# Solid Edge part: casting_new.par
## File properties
Author: Sarvanan
Template: Sync Iso Part.par
Last saved by: Sham
Revision: 25
Application: Solid Edge
Accuracy: 0.990
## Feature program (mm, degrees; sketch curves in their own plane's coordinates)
sketch for "Hole_1" plane through (160.4937, 0.1465, 63.8379) normal (0, 0, 1) x-axis (1, 0, 0)
  hole centre (-0.3699, -0.1465) bore radius 6
hole "Hole_1" diameter 12 through
sketch for "unnamed Hole 1" plane through (81.754, 0.1465, 63.8379) normal (0, 0, 1) x-axis (-1, 0, 0)
  hole centre (-0.3699, -0.1465) bore radius 6
hole "unnamed Hole 1" through
pattern "unnamed Pattern 1" of "Hole_1", "unnamed Hole 1"
Other named dimensions: "Hole_3": FiniteDepth = 8 mm; VBottomAngle = 118 deg; Diameter = 8 mm
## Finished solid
Body 1: solid body, 44 faces, 112 edges, 68 vertices.
  Faces by surface: plane 28, cylinder 10, cone 4, torus 2
  Edges by curve: line 82, circle 25, intersection 5
Bounding box of the edges (mm; curved faces can reach further): 208.000 x 56.000 x 68.000, from (17.1238, -28, -4.1621) to (225.1238, 28, 63.8379).
Cylindrical faces by radius (mm): R4 x1, R5 x4, R6 x2, R24 x1, R54 x2
Conical faces (half-angle, radius in mm at the cone's reference point): 45 deg R6 x4
Toroidal faces (ring radius, tube radius in mm): R62 r8 x2
Planar faces by outward normal: +x 3, +y 3, +z 7, -x 3, -y 3, -z 3, oblique 6
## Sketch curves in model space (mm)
arc centre (121.1238, 0, 63.8379) radius 54 from (169.0819, 24.8199, 63.8379) through (175.1233, -0.2336, 63.8379) to (168.8653, -25.234, 63.8379)
line (169.0819, 24.8199, 63.8379) -> (178.9004, 24.8199, 63.8379)
line (178.9004, 24.8199, 63.8379) -> (178.9004, -25.234, 63.8379)
line (178.9004, -25.234, 63.8379) -> (168.8653, -25.234, 63.8379)
arc centre (121.1238, 0, 63.8379) radius 54 from (169.0819, 24.8199, 63.8379) through (175.1233, -0.2336, 63.8379) to (168.8653, -25.234, 63.8379)
line (169.0819, 24.8199, 63.8379) -> (178.9004, 24.8199, 63.8379)
line (178.9004, 24.8199, 63.8379) -> (178.9004, -25.234, 63.8379)
line (178.9004, -25.234, 63.8379) -> (168.8653, -25.234, 63.8379)
line (63.3473, -25.234, 63.8379) -> (73.3824, -25.234, 63.8379)
line (63.3473, 24.8199, 63.8379) -> (63.3473, -25.234, 63.8379)
line (73.1658, 24.8199, 63.8379) -> (63.3473, 24.8199, 63.8379)
arc centre (121.1238, 0, 63.8379) radius 54 from (73.1658, 24.8199, 63.8379) through (67.1244, -0.2336, 63.8379) to (73.3824, -25.234, 63.8379)
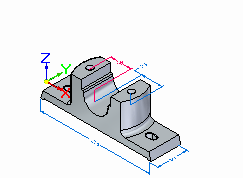
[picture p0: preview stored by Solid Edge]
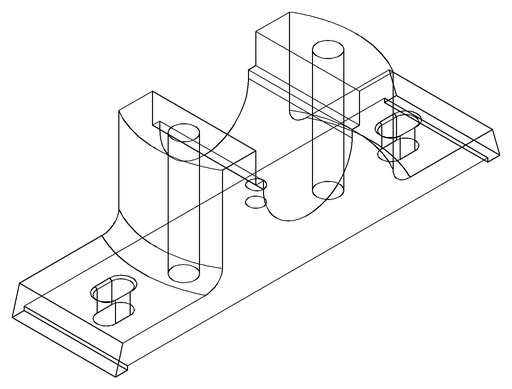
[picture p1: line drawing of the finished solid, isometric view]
